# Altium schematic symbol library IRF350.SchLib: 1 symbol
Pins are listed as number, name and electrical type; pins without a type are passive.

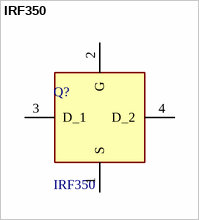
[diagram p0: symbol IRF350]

## IRF350
designator Q?
Trans MOSFET N-CH 400V 14A 3-Pin(2+Tab) TO-3; Manufacturer_Name: Infineon; Geometry.Height: 7.74mm
footprint IRF350
pins: 1 S, 2 G, 3 D_1, 4 D_2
